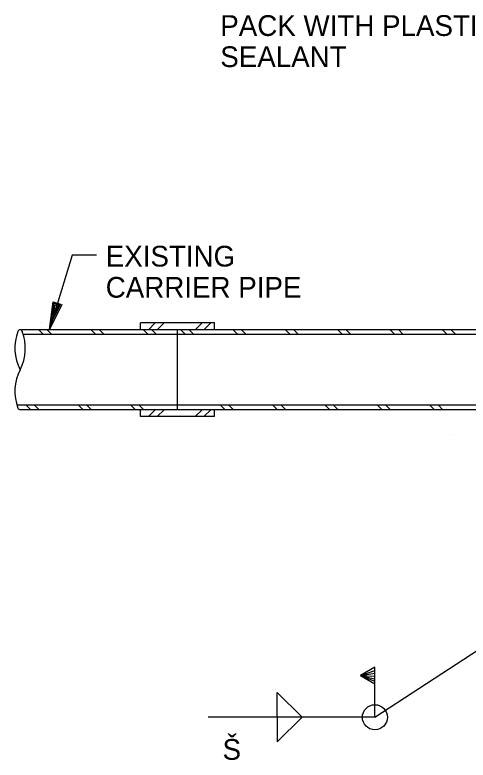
# Model space of a CAD drawing. Extents: x 22339.2 to 22413.4, y 22369.6 to 22418.8.
# Drawn here: x 22376.05 to 22380.13, y 22384.64 to 22391.35 of the extents above; entities that cross this region are included whole.
import ezdxf

# ---------------------------------------------------------------- set-up
doc = ezdxf.new("R2010")
doc.units = 0
for name, color, linetype in [('Level 1', 7, 'Continuous'), ('Level 10', 7, 'Continuous'), ('Level 2', 7, 'Continuous'), ('Level 4', 7, 'Continuous'), ('Level 8', 7, 'Continuous')]:
    doc.layers.add(name, color=color, linetype=linetype)

msp = doc.modelspace()

# ---------------------------------------------------------------- linework, layer by layer
at = {"layer": 'Level 1'}
for p, q in [((22376.2803, 22388.5837), (22376.2803, 22388.5837)), ((22379.9969, 22387.5691), (22379.9969, 22387.5691))]:
    msp.add_line(p, q, dxfattribs=at)
for centre, radius, start, end in [((22376.488, 22388.3504), 0.4356, 159.80644, 206.60705), ((22376.0992, 22388.4934), 0.0213, 20.19356, 159.80644), ((22375.7103, 22388.3504), 0.4356, 333.39295, 20.19356), ((22376.488, 22387.9602), 0.4356, 153.39295, 200.19188), ((22376.0992, 22387.8172), 0.0213, 200.31546, 270)]:
    msp.add_arc(centre, radius, start, end, dxfattribs=at)
at = {"layer": 'Level 10'}
for p, q in [((22379.2918, 22385.0258), (22382.2659, 22386.9672)), ((22379.2918, 22385.4758), (22379.1617, 22385.4008)), ((22379.1617, 22385.4008), (22379.2918, 22385.4477)), ((22379.2918, 22385.0258), (22379.2918, 22385.4758)), ((22379.1617, 22385.4008), (22379.2918, 22385.4222)), ((22379.1617, 22385.4008), (22379.2915, 22385.3258)), ((22379.1617, 22385.4008), (22379.2847, 22385.3943)), ((22379.1617, 22385.4008), (22379.2892, 22385.3712)), ((22379.1617, 22385.4008), (22379.2918, 22385.3502)), ((22378.4132, 22385.2485), (22378.6367, 22385.025)), ((22378.4132, 22385.0235), (22378.4132, 22385.2485)), ((22379.2918, 22385.0258), (22377.7913, 22385.0258)), ((22378.4132, 22385.0282), (22378.4132, 22384.8032)), ((22378.4132, 22384.8032), (22378.6367, 22385.0267))]:
    msp.add_line(p, q, dxfattribs=at)
msp.add_circle((22379.2919, 22385.0258), 0.1125, dxfattribs=at)
at = {"layer": 'Level 2'}
for p, q in [((22377.1826, 22388.514), (22377.1826, 22388.5765)), ((22377.8493, 22388.5765), (22377.1826, 22388.5765)), ((22377.8493, 22388.514), (22377.8493, 22388.5765)), ((22382.7659, 22388.514), (22376.0992, 22388.514)), ((22382.7659, 22388.4724), (22376.1285, 22388.4724)), ((22377.5159, 22387.7953), (22377.5159, 22388.514)), ((22382.7659, 22387.8369), (22376.0702, 22387.8369)), ((22382.7659, 22387.7953), (22376.1004, 22387.7953)), ((22377.1826, 22387.7328), (22377.1826, 22387.7953)), ((22377.8493, 22387.7328), (22377.8493, 22387.7953)), ((22377.8493, 22387.7328), (22377.1826, 22387.7328))]:
    msp.add_line(p, q, dxfattribs=at)
for points in [[(22376.7869, 22389.1854), (22376.5679, 22389.1854), (22376.3625, 22388.5167)], [(22376.4752, 22388.7429), (22376.3625, 22388.5167), (22376.3962, 22388.7672), (22376.4638, 22388.7464), (22376.3829, 22388.583), (22376.4058, 22388.7531), (22376.4492, 22388.7397), (22376.4024, 22388.6467), (22376.4154, 22388.7389), (22376.4333, 22388.7335), (22376.4228, 22388.713)]]:
    msp.add_lwpolyline(points, dxfattribs=at)
at = {"layer": 'Level 8'}
for p, q in [((22376.3829, 22388.583), (22376.3829, 22388.583)), ((22376.3625, 22388.5167), (22376.3625, 22388.5167))]:
    msp.add_line(p, q, dxfattribs=at)
for points in [[(22377.3159, 22388.5765), (22377.2534, 22388.514)], [(22377.3957, 22388.5765), (22377.3332, 22388.514)], [(22377.7379, 22388.5765), (22377.6754, 22388.514)], [(22377.8155, 22388.5765), (22377.753, 22388.514)], [(22376.3082, 22388.4724), (22376.2666, 22388.514)], [(22376.3837, 22388.4724), (22376.342, 22388.514)], [(22376.7796, 22388.4724), (22376.738, 22388.514)], [(22376.8551, 22388.4724), (22376.8134, 22388.514)], [(22377.251, 22388.4724), (22377.2094, 22388.514)], [(22377.3265, 22388.4724), (22377.2848, 22388.514)], [(22377.5886, 22388.4724), (22377.547, 22388.514)], [(22377.6623, 22388.4724), (22377.6206, 22388.514)], [(22378.0583, 22388.4724), (22378.0166, 22388.514)], [(22378.1337, 22388.4724), (22378.092, 22388.514)], [(22378.5297, 22388.4724), (22378.488, 22388.514)], [(22378.6051, 22388.4724), (22378.5634, 22388.514)], [(22379.0011, 22388.4724), (22378.9594, 22388.514)], [(22379.0765, 22388.4724), (22379.0349, 22388.514)], [(22379.4725, 22388.4724), (22379.4308, 22388.514)], [(22379.5479, 22388.4724), (22379.5063, 22388.514)], [(22379.9439, 22388.4724), (22379.9022, 22388.514)], [(22380.0193, 22388.4724), (22379.9777, 22388.514)], [(22376.1952, 22387.7953), (22376.1536, 22387.8369)], [(22376.2707, 22387.7953), (22376.229, 22387.8369)], [(22376.6667, 22387.7953), (22376.625, 22387.8369)], [(22376.7421, 22387.7953), (22376.7004, 22387.8369)], [(22377.1381, 22387.7953), (22377.0964, 22387.8369)], [(22377.2135, 22387.7953), (22377.1718, 22387.8369)], [(22377.3159, 22387.7953), (22377.2534, 22387.7328)], [(22377.3957, 22387.7953), (22377.3332, 22387.7328)], [(22377.7379, 22387.7953), (22377.6754, 22387.7328)], [(22377.8155, 22387.7953), (22377.753, 22387.7328)], [(22377.9441, 22387.7953), (22377.9024, 22387.8369)], [(22378.0195, 22387.7953), (22377.9779, 22387.8369)], [(22378.4155, 22387.7953), (22378.3739, 22387.8369)], [(22378.4909, 22387.7953), (22378.4493, 22387.8369)], [(22378.8869, 22387.7953), (22378.8453, 22387.8369)], [(22378.9624, 22387.7953), (22378.9207, 22387.8369)], [(22379.3583, 22387.7953), (22379.3167, 22387.8369)], [(22379.4338, 22387.7953), (22379.3921, 22387.8369)], [(22379.8297, 22387.7953), (22379.7881, 22387.8369)], [(22379.9052, 22387.7953), (22379.8635, 22387.8369)]]:
    msp.add_lwpolyline(points, dxfattribs=at)

# ---------------------------------------------------------------- texts
at = {"layer": 'Level 4'}
for s, height, p in [('PACK WITH PLASTIC', 0.186667, (22377.9007, 22391.1608)), ('SEALANT', 0.18667, (22377.9007, 22390.8804)), ('EXISTING', 0.18667, (22376.8697, 22389.0842)), ('CARRIER PIPE', 0.186667, (22376.8697, 22388.8038)), ('Š', 0.1867, (22377.9211, 22384.6424))]:
    msp.add_text(s, height=height, dxfattribs=at).set_placement(p)

doc.saveas('drawing.dxf')
